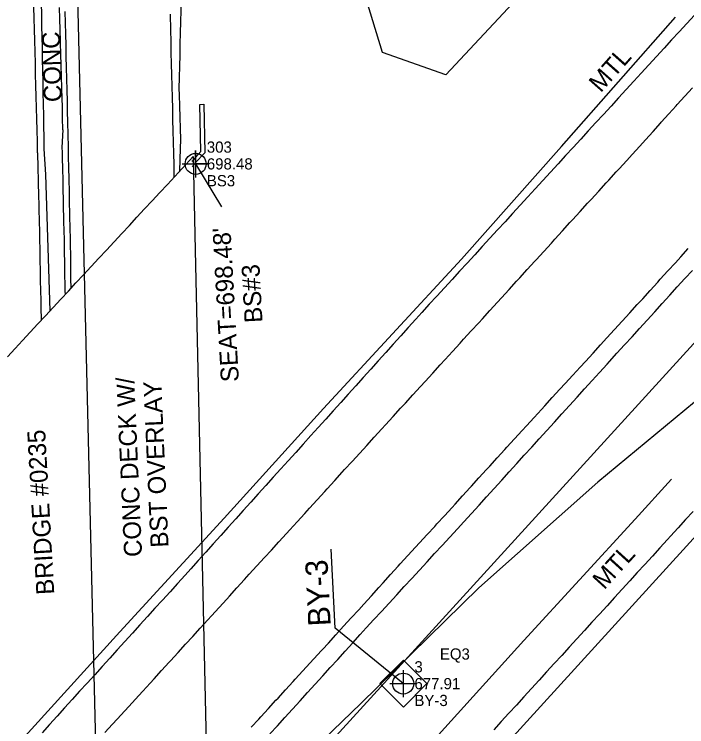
# Model space of a CAD drawing. Extents: x 1806071 to 1809844, y 912722 to 917035.
# Drawn here: x 1807804.9 to 1807955, y 914705.5 to 914864.4 of the extents above; entities that cross this region are included whole.
import ezdxf

# ---------------------------------------------------------------- set-up
doc = ezdxf.new("R2010")
doc.units = 0
for name, color, linetype in [('Cogo Default Point CELL', 7, 'Continuous'), ('COGO Default Point Number', 7, 'Continuous'), ('CTL Supplemental Horizontal and Vertical CELL', 7, 'Continuous'), ('CTL Supplemental Horizontal and Vertical Cogo Comment', 7, 'Continuous'), ('CTL Supplemental Horizontal and Vertical Cogo Elevation', 7, 'Continuous'), ('CTL Supplemental Horizontal and Vertical Cogo Number', 7, 'Continuous'), ('Exist Guardrail', 7, 'Continuous'), ('Exist Guardrail Text', 7, 'Continuous'), ('Exist Horizontal Alignment', 7, 'Continuous'), ('Exist Horizontal Alignment Station Label', 7, 'Continuous'), ('Exist Roads EOP', 7, 'Continuous'), ('Exist Roads EOP Text', 7, 'Continuous'), ('Exist Roads EOT', 7, 'Continuous'), ('Exist Structure Major Bridge Seat Cogo Comment', 7, 'Continuous'), ('Exist Structure Major Bridge Seat Cogo Elevation', 7, 'Continuous'), ('Exist Structure Major Bridge Seat Cogo Number', 7, 'Continuous'), ('Exist Structure Major Bridge Seat Cogo Point CELL', 7, 'Continuous'), ('Exist Structure Major Bridge Seat Top Elevation', 7, 'Continuous'), ('Exist Structure Major Bridge WW', 7, 'Continuous'), ('Exist Structure Major Deck Tunnel Box Culvert', 7, 'Continuous'), ('Exist Structure Major Deck Tunnel Box Culvert Text', 7, 'Continuous'), ('Exist Vegetation Woods Line', 7, 'Continuous')]:
    doc.layers.add(name, color=color, linetype=linetype)

msp = doc.modelspace()

# ---------------------------------------------------------------- linework, layer by layer
at = {"layer": 'Cogo Default Point CELL'}
for points in [[(1807891.73, 914718.07), (1807891.73, 914715.07)], [(1807888.73, 914715.07), (1807891.73, 914715.07)], [(1807891.73, 914715.07), (1807894.73, 914715.07)], [(1807891.73, 914715.07), (1807891.73, 914712.07)]]:
    msp.add_lwpolyline(points, dxfattribs=at)
msp.add_circle((1807891.73, 914715.07), 2.34, dxfattribs=at)
at = {"layer": 'CTL Supplemental Horizontal and Vertical CELL'}
msp.add_line((1807891.73, 914715.07), (1807891.73, 914715.07), dxfattribs=at)
msp.add_lwpolyline([(1807886.51, 914715.08), (1807891.76, 914720.33), (1807897.01, 914715.08), (1807891.76, 914709.83)], close=True, dxfattribs=at)
at = {"layer": 'Exist Guardrail'}
for points in [[(1807756.38, 914648.41), (1807782.68, 914676.23), (1807805.14, 914700.91), (1807828.49, 914726.65), (1807851.81, 914751.97), (1807873.92, 914776.44), (1807904.72, 914809.73), (1807927.04, 914834.91), (1807952.45, 914863.76)], [(1807963.2, 914783.22), (1807935.17, 914760.04), (1807908.57, 914736.42), (1807882.27, 914710.65), (1807863.47, 914692.52), (1807840.66, 914668.07), (1807814.87, 914639.07), (1807789.47, 914611.6), (1807764.43, 914584.29), (1807738.95, 914556.51), (1807714.06, 914529.04), (1807691.49, 914504.04)], [(1807680.51, 914480.34), (1807706.97, 914502.99), (1807740.87, 914533.67), (1807772.15, 914564.62), (1807800.61, 914594.77), (1807854.85, 914654.76), (1807877.02, 914678.62), (1807893.92, 914697.43), (1807918.63, 914724.67), (1807943.49, 914751.73), (1807951.56, 914760.68)]]:
    msp.add_lwpolyline(points, dxfattribs=at)
at = {"layer": 'Exist Horizontal Alignment'}
for p, q in [((1806073.69, 912724.84), (1809374.2, 916346.52)), ((1807829.7, 914431.48), (1807805.85, 915414.67))]:
    msp.add_line(p, q, dxfattribs=at)
at = {"layer": 'Exist Horizontal Alignment Station Label'}
for p, q in [((1807876.54, 914727.45), (1807875.66, 914745.07)), ((1807891.73, 914715.07), (1807876.54, 914727.45))]:
    msp.add_line(p, q, dxfattribs=at)
at = {"layer": 'Exist Roads EOP'}
for points in [[(1807841.9, 914829.44), (1807842.05, 914834.43), (1807842.1, 914836.42), (1807842.03, 914838.91), (1807841.95, 914841.41), (1807841.88, 914843.91), (1807841.8, 914846.41), (1807841.76, 914847.79), (1807841.82, 914850.29), (1807841.87, 914852.78), (1807841.93, 914855.28), (1807841.98, 914857.71), (1807842.04, 914860.21), (1807842.11, 914862.71), (1807842.17, 914865.21), (1807842.16, 914867.22)], [(1807810.94, 914866.81), (1807810.99, 914864.31), (1807811.04, 914861.81), (1807811.09, 914859.31), (1807811.14, 914856.82), (1807811.19, 914854.32), (1807811.24, 914851.82), (1807811.28, 914849.32), (1807811.33, 914846.82), (1807811.38, 914844.32), (1807811.43, 914841.82), (1807811.48, 914839.32), (1807811.52, 914837), (1807811.51, 914834.5), (1807811.51, 914834.38)], [(1807815.78, 914838.63), (1807815.73, 914841.28), (1807815.67, 914843.78), (1807815.64, 914845.51), (1807815.56, 914848), (1807815.49, 914850.5), (1807815.41, 914853), (1807815.34, 914855.5), (1807815.27, 914858), (1807815.26, 914858.38), (1807815.19, 914860.88), (1807815.12, 914863.38), (1807815.05, 914865.88)], [(1807956.69, 914864.16), (1807955, 914862.32), (1807953.31, 914860.48), (1807951.62, 914858.64), (1807949.93, 914856.79), (1807948.24, 914854.95), (1807946.55, 914853.11), (1807944.86, 914851.27), (1807943.17, 914849.42), (1807941.48, 914847.58), (1807939.79, 914845.74), (1807938.1, 914843.9), (1807936.41, 914842.05), (1807934.72, 914840.21), (1807933.03, 914838.37), (1807931.34, 914836.53), (1807929.65, 914834.68), (1807927.96, 914832.84), (1807926.27, 914831), (1807924.58, 914829.16), (1807922.89, 914827.31), (1807921.2, 914825.47), (1807919.51, 914823.63), (1807917.82, 914821.79), (1807916.14, 914819.94), (1807914.45, 914818.1), (1807912.76, 914816.26), (1807911.07, 914814.42), (1807909.38, 914812.57), (1807907.69, 914810.73), (1807906, 914808.89), (1807904.31, 914807.05), (1807902.62, 914805.2), (1807900.93, 914803.36), (1807899.24, 914801.52), (1807897.55, 914799.68), (1807895.86, 914797.83), (1807894.52, 914796.37), (1807892.85, 914794.52), (1807891.17, 914792.66), (1807889.5, 914790.8), (1807887.82, 914788.94), (1807886.15, 914787.09), (1807884.48, 914785.23), (1807882.8, 914783.37), (1807881.13, 914781.52), (1807879.46, 914779.66), (1807877.78, 914777.8), (1807876.11, 914775.95), (1807874.43, 914774.09), (1807872.76, 914772.23), (1807871.09, 914770.38), (1807869.41, 914768.52), (1807867.74, 914766.66), (1807866.06, 914764.8), (1807864.39, 914762.95), (1807862.72, 914761.09), (1807861.04, 914759.23), (1807859.37, 914757.38), (1807857.7, 914755.52), (1807856.02, 914753.66), (1807854.35, 914751.81), (1807852.67, 914749.95), (1807851, 914748.09), (1807849.33, 914746.24), (1807847.65, 914744.38), (1807845.98, 914742.52), (1807844.31, 914740.66), (1807843.05, 914739.27), (1807841.37, 914737.42), (1807839.69, 914735.57), (1807838.01, 914733.72), (1807836.33, 914731.87), (1807834.65, 914730.02), (1807832.97, 914728.16), (1807831.29, 914726.31), (1807829.61, 914724.46), (1807827.93, 914722.61), (1807826.25, 914720.76), (1807824.57, 914718.91), (1807822.89, 914717.06), (1807821.21, 914715.21), (1807819.53, 914713.36), (1807817.85, 914711.5), (1807816.17, 914709.65), (1807814.49, 914707.8), (1807812.81, 914705.95), (1807811.13, 914704.1)], [(1807815.77, 914838.6), (1807815.57, 914834.62), (1807815.59, 914833.62), (1807815.62, 914832.62), (1807815.64, 914831.62), (1807815.67, 914830.62), (1807815.69, 914829.62), (1807815.74, 914827.63), (1807815.76, 914826.64), (1807815.77, 914825.64), (1807815.78, 914824.64), (1807815.83, 914823.64), (1807815.85, 914821.64), (1807815.91, 914818.62), (1807815.94, 914817.62), (1807815.98, 914816.62), (1807816.07, 914813.62), (1807816.1, 914812.65), (1807816.15, 914807.65), (1807816.24, 914802.62), (1807816.32, 914801.93)], [(1807811.51, 914834.35), (1807811.9, 914828.64), (1807812.91, 914798.2)], [(1807861.99, 914703.84), (1807863.67, 914705.69), (1807865.35, 914707.54), (1807867.03, 914709.39), (1807868.71, 914711.24), (1807870.39, 914713.09), (1807872.07, 914714.94), (1807873.76, 914716.79), (1807875.44, 914718.64), (1807877.12, 914720.49), (1807878.8, 914722.34), (1807880.48, 914724.19), (1807882.16, 914726.04), (1807883.49, 914727.51), (1807885.19, 914729.35), (1807886.88, 914731.19), (1807888.57, 914733.03), (1807890.27, 914734.87), (1807891.96, 914736.71), (1807893.65, 914738.55), (1807895.35, 914740.39), (1807897.04, 914742.23), (1807898.73, 914744.07), (1807900.42, 914745.91), (1807902.12, 914747.75), (1807903.81, 914749.58), (1807905.29, 914751.19), (1807906.97, 914753.04), (1807908.65, 914754.89), (1807910.33, 914756.74), (1807912.02, 914758.6), (1807913.7, 914760.45), (1807915.38, 914762.3), (1807917.06, 914764.15), (1807918.74, 914766), (1807920.42, 914767.85), (1807922.1, 914769.7), (1807923.78, 914771.55), (1807925.46, 914773.4), (1807927.14, 914775.25), (1807928.83, 914777.1), (1807930.51, 914778.95), (1807932.19, 914780.8), (1807933.87, 914782.65), (1807935.55, 914784.5), (1807937.23, 914786.35), (1807937.74, 914786.92), (1807939.42, 914788.76), (1807941.11, 914790.61), (1807942.79, 914792.46), (1807944.47, 914794.31), (1807946.16, 914796.16), (1807947.84, 914798), (1807949.52, 914799.85), (1807951.21, 914801.7), (1807952.89, 914803.55), (1807954.57, 914805.4), (1807956.26, 914807.25)], [(1807956.42, 914753.5), (1807954.74, 914751.65), (1807953.06, 914749.8), (1807951.38, 914747.95), (1807950.71, 914747.22), (1807949.02, 914745.37), (1807947.34, 914743.52), (1807945.65, 914741.68), (1807943.96, 914739.83), (1807942.28, 914737.99), (1807940.59, 914736.14), (1807938.9, 914734.3), (1807937.22, 914732.45), (1807935.53, 914730.6), (1807933.85, 914728.76), (1807932.16, 914726.91), (1807930.47, 914725.07), (1807928.79, 914723.22), (1807927.1, 914721.38), (1807925.41, 914719.53), (1807923.73, 914717.69), (1807922.04, 914715.84), (1807920.36, 914713.99), (1807918.67, 914712.15), (1807916.98, 914710.3), (1807915.3, 914708.46), (1807913.61, 914706.61), (1807911.92, 914704.77)]]:
    msp.add_lwpolyline(points, dxfattribs=at)
at = {"layer": 'Exist Roads EOT'}
msp.add_line((1807617.6, 914375.74), (1808224.93, 915041.78), dxfattribs=at)
for points in [[(1807810.15, 914833.5), (1807810.09, 914836), (1807810.03, 914838.5), (1807809.96, 914841), (1807809.9, 914843.5), (1807809.84, 914846), (1807809.77, 914848.5), (1807809.71, 914851), (1807809.65, 914853.49), (1807809.58, 914855.99), (1807809.52, 914858.49), (1807809.46, 914860.99), (1807809.39, 914863.49), (1807809.33, 914865.99)], [(1807816.23, 914864.97), (1807816.29, 914862.47), (1807816.35, 914859.97), (1807816.41, 914857.47), (1807816.47, 914854.97), (1807816.53, 914852.47), (1807816.59, 914849.97), (1807816.65, 914847.47), (1807816.71, 914844.97), (1807816.77, 914842.47), (1807816.82, 914840.6)], [(1807839.71, 914864.37), (1807839.79, 914860.83), (1807839.85, 914858.33), (1807839.91, 914855.83), (1807839.97, 914853.33), (1807840.03, 914850.83), (1807840.09, 914848.33), (1807840.15, 914845.83), (1807840.21, 914843.34), (1807840.27, 914840.84), (1807840.33, 914838.34), (1807840.39, 914835.84), (1807840.45, 914833.34), (1807840.51, 914830.84), (1807840.57, 914828.01)], [(1807825.18, 914704.16), (1807826.86, 914706.02), (1807827.91, 914707.18), (1807829.6, 914709.03), (1807831.29, 914710.87), (1807831.9, 914711.53), (1807833.59, 914713.37), (1807835.28, 914715.21), (1807836.13, 914716.14), (1807837.81, 914717.99), (1807839.5, 914719.83), (1807839.8, 914720.17), (1807841.49, 914722.01), (1807843.18, 914723.86), (1807844.76, 914725.58), (1807846.45, 914727.43), (1807848.14, 914729.27), (1807848.98, 914730.19), (1807850.66, 914732.04), (1807852.35, 914733.88), (1807852.95, 914734.55), (1807854.62, 914736.41), (1807856.3, 914738.27), (1807857.39, 914739.49), (1807859.09, 914741.33), (1807860.78, 914743.17), (1807862.33, 914744.86), (1807864.01, 914746.71), (1807865.69, 914748.56), (1807866.41, 914749.35), (1807868.1, 914751.19), (1807869.79, 914753.04), (1807870.85, 914754.2), (1807872.53, 914756.04), (1807874.22, 914757.89), (1807874.79, 914758.51), (1807876.46, 914760.36), (1807878.14, 914762.22), (1807878.66, 914762.8), (1807880.35, 914764.64), (1807882.04, 914766.49), (1807883.6, 914768.2), (1807885.28, 914770.05), (1807886.97, 914771.9), (1807887.78, 914772.79), (1807889.47, 914774.64), (1807891.16, 914776.48), (1807892.21, 914777.62), (1807893.89, 914779.47), (1807895.58, 914781.32), (1807896.63, 914782.48), (1807898.31, 914784.32), (1807900, 914786.17), (1807901.06, 914787.34), (1807902.74, 914789.18), (1807904.43, 914791.02), (1807905.21, 914791.88), (1807906.9, 914793.73), (1807908.58, 914795.57), (1807909.39, 914796.46), (1807911.08, 914798.3), (1807912.77, 914800.15), (1807913.66, 914801.12), (1807915.34, 914802.97), (1807917.03, 914804.81), (1807917.73, 914805.58), (1807919.42, 914807.42), (1807921.1, 914809.27), (1807921.42, 914809.61), (1807923.11, 914811.46), (1807924.79, 914813.3), (1807925.59, 914814.18), (1807927.26, 914816.04), (1807928.93, 914817.9), (1807929.5, 914818.54), (1807931.18, 914820.38), (1807932.87, 914822.23), (1807933.65, 914823.08), (1807935.35, 914824.92), (1807937.04, 914826.76), (1807937.58, 914827.34), (1807939.26, 914829.2), (1807939.92, 914829.93), (1807941.61, 914831.78), (1807942.84, 914833.13), (1807944.52, 914834.98), (1807945.81, 914836.4), (1807947.49, 914838.25), (1807949.17, 914840.1), (1807949.32, 914840.27), (1807950.99, 914842.13), (1807952.66, 914843.98), (1807952.89, 914844.23), (1807954.57, 914846.08), (1807956.26, 914847.93)], [(1807816.82, 914840.58), (1807816.88, 914837.16), (1807816.93, 914835.13), (1807817, 914832.63), (1807817.06, 914830.13), (1807817.12, 914827.64), (1807817.13, 914827.45), (1807817.16, 914824.95), (1807817.19, 914822.45), (1807817.23, 914819.95), (1807817.24, 914819.24), (1807817.31, 914816.74), (1807817.39, 914814.24), (1807817.43, 914813.02), (1807817.46, 914810.52), (1807817.48, 914808.02), (1807817.51, 914805.52), (1807817.53, 914803.18)], [(1807810.15, 914833.48), (1807810.21, 914830.12), (1807810.21, 914829.97), (1807810.24, 914827.47), (1807810.26, 914826.64), (1807810.33, 914824.14), (1807810.4, 914821.64), (1807810.43, 914820.79), (1807810.48, 914818.29), (1807810.54, 914815.79), (1807810.57, 914814.27), (1807810.62, 914811.77), (1807810.66, 914809.27), (1807810.69, 914807.35), (1807810.75, 914804.85), (1807810.8, 914802.88), (1807810.86, 914800.38), (1807810.89, 914799.09), (1807810.93, 914796.06)], [(1807857.83, 914705.35), (1807859.53, 914707.18), (1807859.97, 914707.66), (1807861.65, 914709.5), (1807863.34, 914711.35), (1807863.8, 914711.85), (1807865.48, 914713.71), (1807867.15, 914715.56), (1807867.62, 914716.08), (1807869.32, 914717.91), (1807870.1, 914718.77), (1807871.8, 914720.6), (1807873.5, 914722.44), (1807873.71, 914722.66), (1807875.05, 914724.13), (1807876.72, 914725.99), (1807878.42, 914727.88), (1807880.11, 914729.72), (1807881.79, 914731.56), (1807882.93, 914732.81), (1807884.62, 914734.65), (1807886.31, 914736.5), (1807887.24, 914737.52), (1807888.91, 914739.38), (1807890.58, 914741.24), (1807891.07, 914741.8), (1807892.76, 914743.64), (1807894.45, 914745.49), (1807895.36, 914746.48), (1807897.05, 914748.32), (1807898.75, 914750.15), (1807899.23, 914750.68), (1807900.92, 914752.52), (1807902.62, 914754.36), (1807903.31, 914755.12), (1807904.99, 914756.98), (1807906.67, 914758.83), (1807906.93, 914759.12), (1807908.61, 914760.97), (1807910.3, 914762.82), (1807911.02, 914763.61), (1807912.7, 914765.46), (1807914.39, 914767.31), (1807914.86, 914767.84), (1807916.56, 914769.68), (1807918.25, 914771.51), (1807919.23, 914772.57), (1807920.93, 914774.41), (1807922.62, 914776.25), (1807923.32, 914777.01), (1807925, 914778.86), (1807926.68, 914780.72), (1807927.86, 914782.02), (1807929.55, 914783.86), (1807931.25, 914785.69), (1807932.4, 914786.94), (1807934.08, 914788.78), (1807935.77, 914790.63), (1807937.19, 914792.19), (1807938.86, 914794.05), (1807940.57, 914795.95), (1807942.27, 914797.78), (1807943.96, 914799.62), (1807945.17, 914800.93), (1807946.84, 914802.79), (1807948.51, 914804.65), (1807949.07, 914805.27), (1807950.76, 914807.11), (1807952.46, 914808.95), (1807953.64, 914810.24), (1807955.32, 914812.1)], [(1807857.83, 914705.35), (1807859.53, 914707.18), (1807859.97, 914707.66), (1807861.65, 914709.5), (1807863.34, 914711.35), (1807863.8, 914711.85), (1807865.48, 914713.71), (1807867.15, 914715.56), (1807867.62, 914716.08), (1807869.32, 914717.91), (1807870.1, 914718.77), (1807871.8, 914720.6), (1807873.5, 914722.44), (1807873.71, 914722.66), (1807875.05, 914724.13), (1807876.72, 914725.99), (1807878.42, 914727.88), (1807880.11, 914729.72), (1807881.79, 914731.56), (1807882.93, 914732.81), (1807884.62, 914734.65), (1807886.31, 914736.5), (1807887.24, 914737.52), (1807888.91, 914739.38), (1807890.58, 914741.24), (1807891.07, 914741.8), (1807892.76, 914743.64), (1807894.45, 914745.49), (1807895.36, 914746.48), (1807897.05, 914748.32), (1807898.75, 914750.15), (1807899.23, 914750.68), (1807900.92, 914752.52), (1807902.62, 914754.36), (1807903.31, 914755.12), (1807904.99, 914756.98), (1807906.67, 914758.83), (1807906.93, 914759.12), (1807908.61, 914760.97), (1807910.3, 914762.82), (1807911.02, 914763.61), (1807912.7, 914765.46), (1807914.39, 914767.31), (1807914.86, 914767.84), (1807916.56, 914769.68), (1807918.25, 914771.51), (1807919.23, 914772.57), (1807920.93, 914774.41), (1807922.62, 914776.25), (1807923.32, 914777.01), (1807925, 914778.86), (1807926.68, 914780.72), (1807927.86, 914782.02), (1807929.55, 914783.86), (1807931.25, 914785.69), (1807932.4, 914786.94), (1807934.08, 914788.78), (1807935.77, 914790.63), (1807937.19, 914792.19), (1807938.86, 914794.05), (1807940.57, 914795.95), (1807942.27, 914797.78), (1807943.96, 914799.62), (1807945.17, 914800.93), (1807946.84, 914802.79), (1807948.51, 914804.65), (1807949.07, 914805.27), (1807950.76, 914807.11), (1807952.46, 914808.95), (1807953.64, 914810.24), (1807955.32, 914812.1)]]:
    msp.add_lwpolyline(points, dxfattribs=at)
at = {"layer": 'Exist Structure Major Bridge Seat Cogo Point CELL'}
msp.add_lwpolyline([(1807842.41, 914831), (1807848.41, 914831), (1807845.41, 914831), (1807845.41, 914834), (1807845.41, 914828)], dxfattribs=at)
msp.add_circle((1807845.41, 914831), 2.34, dxfattribs=at)
at = {"layer": 'Exist Structure Major Bridge Seat Top Elevation'}
msp.add_line((1807845.41, 914831), (1807851.18, 914821.42), dxfattribs=at)
at = {"layer": 'Exist Structure Major Bridge WW'}
for points in [[(1807844.59, 914831.6), (1807844.76, 914831.77), (1807846.6, 914833.76), (1807846.33, 914844.26)], [(1807846.33, 914844.26), (1807847.22, 914844.31), (1807847.43, 914833.49), (1807845.33, 914831.24), (1807844.6, 914830.32)]]:
    msp.add_lwpolyline(points, dxfattribs=at)
at = {"layer": 'Exist Structure Major Deck Tunnel Box Culvert'}
msp.add_lwpolyline([(1807803.41, 914787.96), (1807805.11, 914789.79), (1807806.81, 914791.62), (1807808.51, 914793.46), (1807810.21, 914795.29), (1807811.91, 914797.12), (1807813.61, 914798.95), (1807815.31, 914800.79), (1807817.01, 914802.62), (1807818.71, 914804.45), (1807820.41, 914806.28), (1807822.11, 914808.12), (1807823.82, 914809.95), (1807825.52, 914811.78), (1807827.22, 914813.61), (1807828.92, 914815.45), (1807830.62, 914817.28), (1807832.32, 914819.11), (1807834.02, 914820.94), (1807835.72, 914822.78), (1807837.42, 914824.61), (1807839.12, 914826.44), (1807844.85, 914832.62), (1807845.32, 914811.76), (1807845.76, 914791.76), (1807846.21, 914771.77), (1807846.65, 914751.77), (1807847.1, 914731.78), (1807847.54, 914711.78), (1807847.99, 914691.79)], dxfattribs=at)
at = {"layer": 'Exist Vegetation Woods Line'}
msp.add_lwpolyline([(1808182.81, 915194.98), (1808194.59, 915182.96), (1808123.23, 915089.31), (1808048.18, 915019.02), (1807959.95, 914913.66), (1807901.26, 914850.85), (1807887.11, 914855.83), (1807879.29, 914881.53), (1807880.44, 914923.49), (1807894.04, 914955.02), (1807915.84, 914974.97), (1807953.6, 915004.2), (1807991.45, 915032.47), (1808031.33, 915065.58), (1808068.31, 915096.93), (1808108.92, 915131.55), (1808145.7, 915163.42), (1808182.81, 915194.98)], dxfattribs=at)

# ---------------------------------------------------------------- texts
at = {"layer": 'COGO Default Point Number'}
msp.add_text('EQ3', height=2.5, dxfattribs=at).set_placement((1807899.91, 914720.43))
at = {"layer": 'CTL Supplemental Horizontal and Vertical Cogo Comment'}
msp.add_text('BY-3', height=2.5, dxfattribs=at).set_placement((1807894.23, 914710.07))
at = {"layer": 'CTL Supplemental Horizontal and Vertical Cogo Elevation'}
msp.add_text('677.91', height=2.5, dxfattribs=at).set_placement((1807894.23, 914713.82))
at = {"layer": 'CTL Supplemental Horizontal and Vertical Cogo Number'}
msp.add_text('3', height=2.5, dxfattribs=at).set_placement((1807894.23, 914717.57))
at = {"layer": 'Exist Guardrail Text'}
for rotation, p in [(48.4637, (1807935.8, 914846.71)), (47.788, (1807936.57, 914735.87))]:
    msp.add_text('MTL', height=4, rotation=rotation, dxfattribs=at).set_placement(p)
at = {"layer": 'Exist Horizontal Alignment Station Label'}
msp.add_text('BY-3', height=5, rotation=92.8422, dxfattribs=at).set_placement((1807875.56, 914727.99))
at = {"layer": 'Exist Roads EOP Text'}
msp.add_text('CONC', height=4, rotation=91.6838, dxfattribs=at).set_placement((1807815.56, 914844.84))
at = {"layer": 'Exist Structure Major Bridge Seat Cogo Comment'}
msp.add_text('BS3', height=2.5, dxfattribs=at).set_placement((1807847.91, 914826))
at = {"layer": 'Exist Structure Major Bridge Seat Cogo Elevation'}
msp.add_text('698.48', height=2.5, dxfattribs=at).set_placement((1807847.91, 914829.75))
at = {"layer": 'Exist Structure Major Bridge Seat Cogo Number'}
msp.add_text('303', height=2.5, dxfattribs=at).set_placement((1807847.91, 914833.5))
at = {"layer": 'Exist Structure Major Bridge Seat Top Elevation'}
for s, p in [("SEAT=698.48'", (1807855.07, 914782.46)), ('BS#3', (1807860.35, 914795.65))]:
    msp.add_text(s, height=4, rotation=93.1745, dxfattribs=at).set_placement(p)
at = {"layer": 'Exist Structure Major Deck Tunnel Box Culvert Text'}
for s, rotation, p in [('CONC DECK W/', 92.5479, (1807833.47, 914743.41)), ('BST OVERLAY', 92.5479, (1807839.38, 914745.5)), ('BRIDGE #0235', 93.2239, (1807813.88, 914735))]:
    msp.add_text(s, height=4, rotation=rotation, dxfattribs=at).set_placement(p)

doc.saveas('drawing.dxf')
